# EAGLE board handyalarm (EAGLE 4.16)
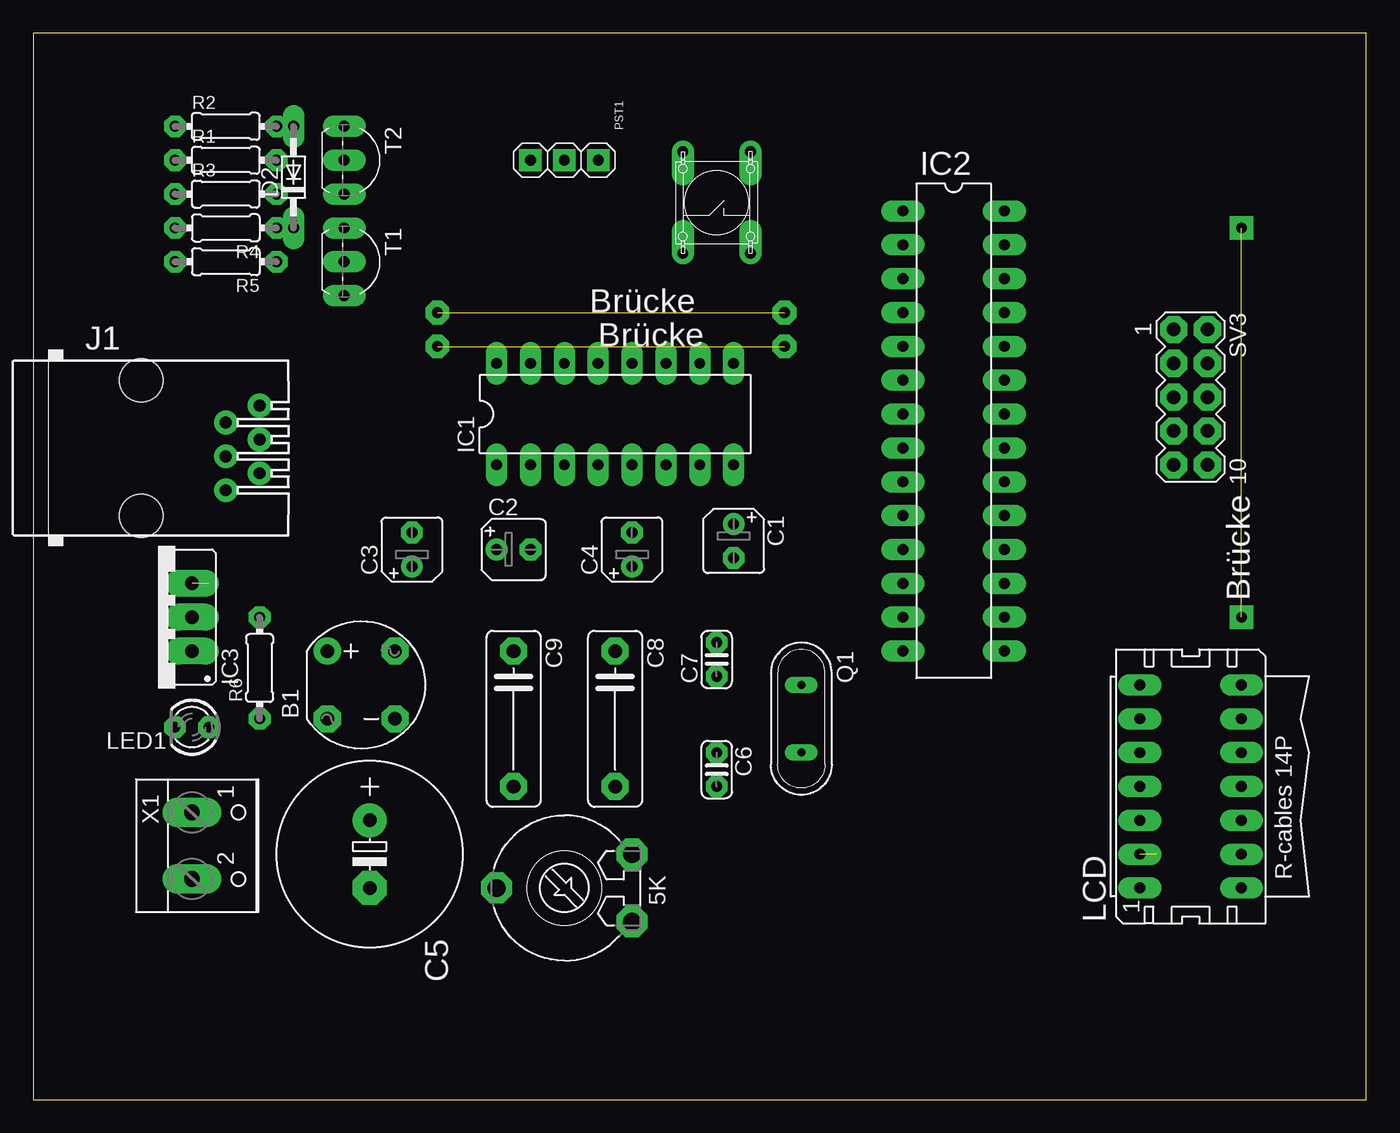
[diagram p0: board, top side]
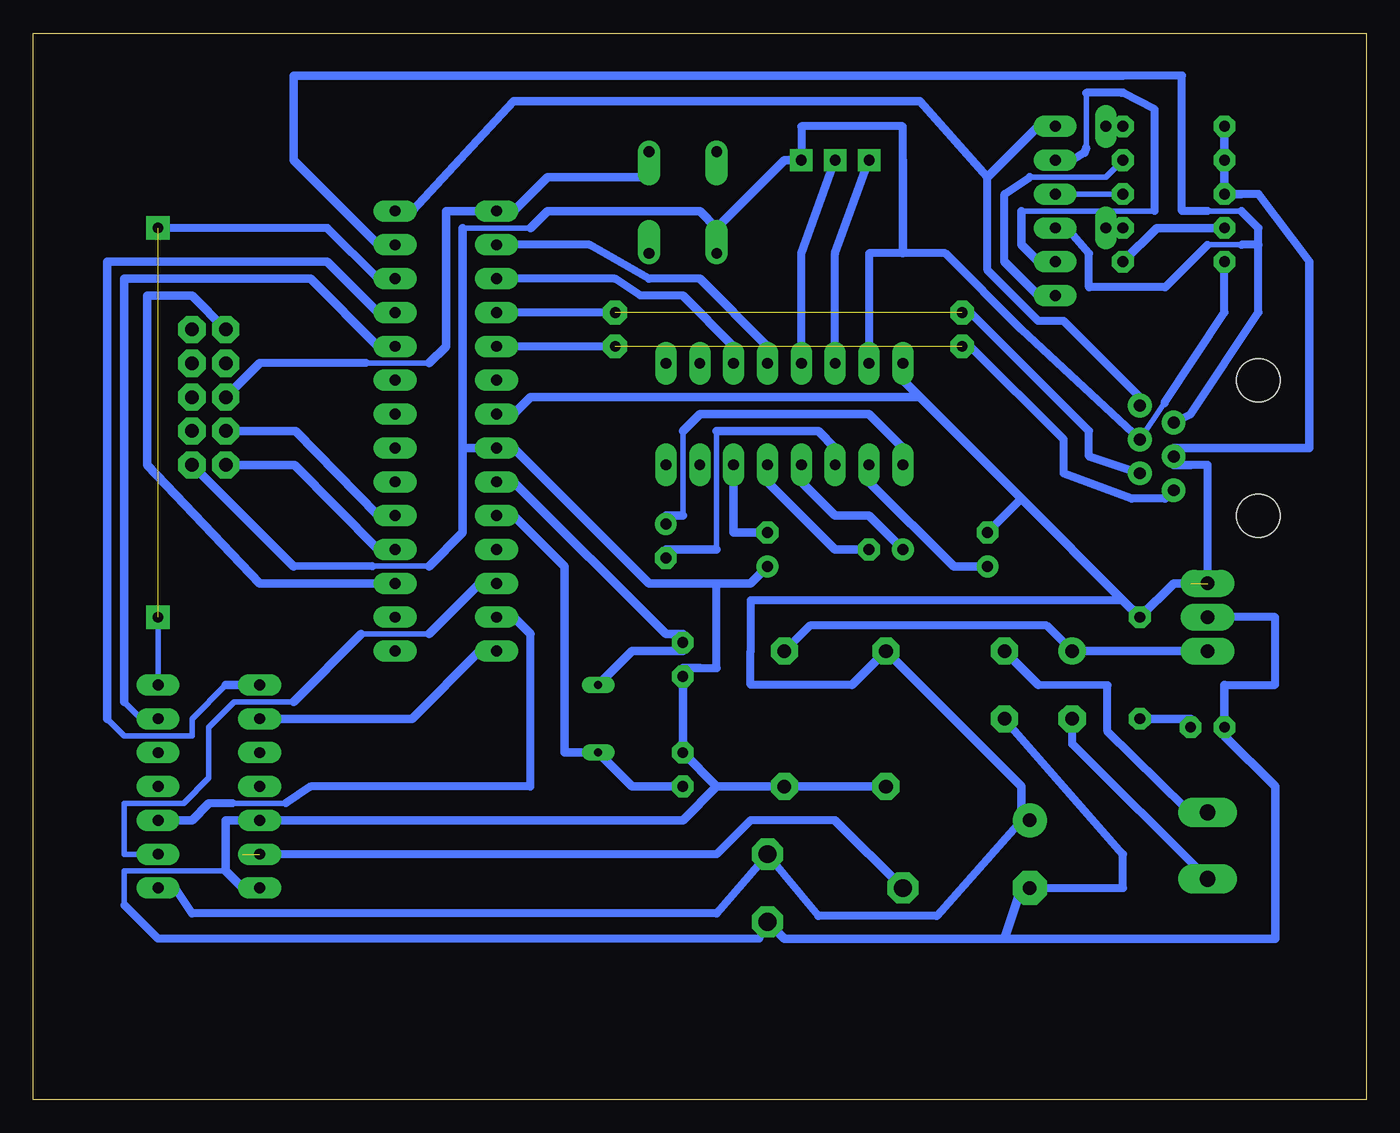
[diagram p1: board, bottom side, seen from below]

Size 100 x 80 mm. Coordinates in mm from the lower left corner, seen from the top.
Outline: 0,0 100,0 100,80 0,80 0,0
Copper layers (1*16): Top 0.035mm / dielectric 1.5mm / Bottom 0.035mm
Design rules "0,6mmleiterbahn": minimum track width 25mil, minimum drill 24mil, track to track 20mil, track to pad 20mil, pad to pad 20mil, via to via 8mil, smd to smd 8mil, copper to edge 40mil, drill to drill 8mil, minimum pad ring 10mil, minimum via ring 8mil, stop-mask expansion 4mil, vias tented up to drill 0mil, thermal gap 10mil

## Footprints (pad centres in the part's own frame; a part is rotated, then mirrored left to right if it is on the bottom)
LI10 = drill 1.321 octagon: A -2.54,-5.08; E 2.54,-5.08; S 0,5.08
RB1A = drill 1.016 round: + -2.54,2.54 | drill 1.016 octagon: - 2.54,-2.54; AC1 2.54,2.54; AC2 -2.54,-2.54
B45181A = drill 0.813 pad 1.6 round: + -1.27,0 | drill 0.813 pad 1.6 octagon: - 1.27,0
E5-13 = drill 1.016 pad 2.54 round: + -2.54,0 | drill 1.016 pad 2.54 octagon: - 2.54,0
C025-024X044 = drill 0.813 octagon: 1 -1.27,0; 2 1.27,0
C102-043X133 = drill 1.016 octagon: 1 -5.08,0; 2 5.08,0
DO34-7 = drill 0.813 long: A 3.81,0; C -3.81,0
DIL16 = drill 0.813 long: 1 -8.89,-3.81; 2 -6.35,-3.81; 3 -3.81,-3.81; 4 -1.27,-3.81; 5 1.27,-3.81; 6 3.81,-3.81; 7 6.35,-3.81; 8 8.89,-3.81; 9 8.89,3.81; 10 6.35,3.81; 11 3.81,3.81; 12 1.27,3.81; 13 -1.27,3.81; 14 -3.81,3.81; 15 -6.35,3.81; 16 -8.89,3.81
DIL28-3 = drill 0.813 long: 1 -16.51,-3.81; 2 -13.97,-3.81; 3 -11.43,-3.81; 4 -8.89,-3.81; 5 -6.35,-3.81; 6 -3.81,-3.81; 7 -1.27,-3.81; 8 1.27,-3.81; 9 3.81,-3.81; 10 6.35,-3.81; 11 8.89,-3.81; 12 11.43,-3.81; 13 13.97,-3.81; 14 16.51,-3.81; 15 16.51,3.81; 16 13.97,3.81; 17 11.43,3.81; 18 8.89,3.81; 19 6.35,3.81; 20 3.81,3.81; 21 1.27,3.81; 22 -1.27,3.81; 23 -3.81,3.81; 24 -6.35,3.81; 25 -8.89,3.81; 26 -11.43,3.81; 27 -13.97,3.81; 28 -16.51,3.81
78XXS = drill 1.016 long: GND 0,-2.54; IN -2.54,-2.54; OUT 2.54,-2.54
520250-3 = drill 0.889 round: 1 -3.175,8.89; 2 -1.905,6.35; 3 -0.635,8.89; 4 0.635,6.35; 5 1.905,8.89; 6 3.175,6.35 | hole 3.251: -5.08,0; 5.08,0
14P = drill 0.813 long: 1 -7.62,3.81; 2 -7.62,-3.81; 3 -5.08,3.81; 4 -5.08,-3.81; 5 -2.54,3.81; 6 -2.54,-3.81; 7 0,3.81; 8 0,-3.81; 9 2.54,3.81; 10 2.54,-3.81; 11 5.08,3.81; 12 5.08,-3.81; 13 7.62,3.81; 14 7.62,-3.81
LED3MM = drill 0.813 octagon: A -1.27,0; K 1.27,0
PFST-1-3 = drill 0.8 pad 1.676 square: 1 2.54,2.54; 2 2.54,0; 3 2.54,-2.54
QS = drill 0.61 long: 1 -2.54,0; 2 2.54,0
0204/7 = drill 0.813 octagon: 1 -3.81,0; 2 3.81,0
MA05-2 = drill 1.016 octagon: 1 -5.08,-1.27; 2 -5.08,1.27; 3 -2.54,-1.27; 4 -2.54,1.27; 5 0,-1.27; 6 0,1.27; 7 2.54,-1.27; 8 2.54,1.27; 9 5.08,-1.27; 10 5.08,1.27
TO92-EBC = drill 0.813 long: B 0,-1.27; C -2.54,-1.27; E 2.54,-1.27
TASTER = drill 0.8 pad 1.676 offset: 1 -2.54,2.54; 2 5.08,2.54; 3 -2.54,-2.54; 4 5.08,-2.54
W237-102 = drill 1.194 long: 1 -2.5,-1.27; 2 2.5,-1.27

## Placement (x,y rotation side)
5K  [LI10]  39.84,15.87 90 top
B1  RECTIFIER-RB1A  [RB1A]  24.6,31.11 0 top
C1  [B45181A]  52.54,41.91 270 top
C2  [B45181A]  36.03,41.27 0 top
C3  [B45181A]  28.41,41.27 90 top
C4  [B45181A]  44.92,41.27 90 top
C5  [E5-13]  25.23,18.41 270 top
C6  22p  [C025-024X044]  51.27,24.76 270 top
C7  22p  [C025-024X044]  51.27,33.02 90 top
C8  100n  [C102-043X133]  43.65,28.57 270 top
C9  100n  [C102-043X133]  36.03,28.57 270 top
D2  BAS15  [DO34-7]  19.52,69.21 90 top
IC1  MAX232  [DIL16]  43.65,51.43 0 top
IC2  MEGA8-P  [DIL28-3]  69.05,50.16 270 top
IC3  [78XXS]  9.36,36.19 90 top
J1  [520250-3]  8.09,48.89 270 top
LCD  [14P]  86.83,23.49 90 top
LED1  [LED3MM]  11.9,27.93 180 top
PST1  RS232  [PFST-1-3]  39.84,73.02 270 top
Q1  8MHZ  [QS]  57.62,28.57 270 top
R1  100  [0204/7]  14.44,70.48 0 top
R2  1k  [0204/7]  14.44,73.02 0 top
R3  100  [0204/7]  14.44,67.94 0 top
R4  3k3  [0204/7]  14.44,65.4 180 top
R5  330  [0204/7]  14.44,62.86 180 top
R6  [0204/7]  16.98,32.38 90 top
SV3  ISP  [MA05-2]  86.83,52.7 270 top
T1  BC557  [TO92-EBC]  24.6,62.86 270 top
T2  BC557  [TO92-EBC]  24.6,70.48 270 top
TA1  TASTER  [TASTER]  51.27,66.03 90 top
X1  [W237-102]  13.17,19.04 270 top

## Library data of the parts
5K = pot
B1 = rectifier
C1-C7 IC1-IC3 LED1 R1-R6 X1 = mega8modul
C8 C9 = rcl
D2 = diode
J1 = con-amp
LCD = con-dil
PST1 TA1 = mylib-gg
Q1 = special
SV3 = con-lstb
T1 T2 = transistor

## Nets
GND: 5K.A B1.- C4.+ C5.- C6.1 C7.1 C8.2 C9.2 IC1.15 IC2.8 IC3.GND J1.3 LCD.1 LCD.5 LED1.K PST1.1 R5.2 SV3.10 TA1.1
N$1: R1.2 T1.E
N$2: D2.A R2.2
N$3: D2.C R4.1 T1.B T2.B
N$4: R3.2 T2.E
N$5: R4.2 R5.1
N$6: C3.+ IC1.2
N$7: IC2.27 J1.2 T1.C
N$8: IC2.28 J1.1 T2.C
N$9: C4.- IC1.6
N$10: C1.- IC1.3
N$11: C1.+ IC1.1
N$12: C2.+ IC1.4
N$13: C2.- IC1.5
N$14: IC1.13 PST1.2
N$15: IC1.14 PST1.3
N$16: IC1.11 IC2.3
N$17: IC1.12 IC2.2
N$18: C7.2 IC2.9 Q1.1
N$19: IC2.25 LCD.13
N$20: IC2.14 LCD.11
N$21: IC2.4 J1.5
N$22: IC2.26 LCD.14
N$23: IC2.24 LCD.12
N$24: IC2.13 LCD.6
N$25: IC2.12 LCD.4
N$26: IC2.1 SV3.5 TA1.4
N$27: B1.+ C8.1 IC3.IN
N$28: B1.AC1 X1.1
N$29: B1.AC2 X1.2
N$30: LED1.A R6.1
N$31: IC2.5 J1.6
N$32: C6.2 IC2.10 Q1.2
N$49: IC2.17 SV3.1
N$50: IC2.18 SV3.9
N$51: IC2.19 SV3.7
N$53: 5K.S LCD.3
VCC: 5K.E C3.- C5.+ C9.1 IC1.16 IC2.7 IC3.OUT J1.4 LCD.2 R1.1 R2.1 R3.1 R6.2

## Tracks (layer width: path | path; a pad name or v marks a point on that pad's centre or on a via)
GND
  Bottom 0.406: 67.78,65.4 62.7,65.4 | 93.18,14.6 93.18,17.14 85.56,17.14 | 70.32,40 70.34,40.01 74.57,40.01 | J1.3 15.14,52.26
  Bottom 0.61: 37.3,55.88 37.3,63.5 34.76,63.5 31.58,63.5 25.87,57.78 J1.3 | R5.2 10.63,59.05 15.14,52.26 | 5K.A 45.55,12.06 90.64,12.06 90.66,12.1 93.18,14.6 | B1.- 18.25,18.41 18.25,15.87 25.87,15.87 | 50,32.38 48.73,32.38 48.73,38.73 | 10.63,31.11 6.82,31.11 6.82,36.19 IC3.GND | 70.32,40 70.3,40.01 | 74.57,40.01 80.48,40 | 34.76,70.48 34.76,73.02 42.38,73.02 PST1.1
  Bottom 0.635: 10.63,31.11 LED1.K 10.63,27.3 6.82,23.49 6.82,12.06 27.14,12.06 | 5K.A 43.65,12.06 27.14,12.06 | 27.14,12.06 25.87,15.87 C5.- | 48.73,65.4 43.65,70.48 PST1.1 | IC1.15 37.3,55.88 37.3,56.51 | 34.76,63.5 34.76,70.48 | C4.+ 46.19,38.73 48.73,38.73 53.81,38.73 63.97,48.89 IC2.8 67.78,48.89 | 80.48,40 SV3.10 | 70.32,40 67.78,42.54 67.78,48.89 | LCD.1 84.29,15.87 85.56,17.14 85.56,20.95 LCD.5 51.27,20.95 48.73,23.49 | C9.2 C8.2 48.73,23.49 | 48.73,23.49 C6.1 C7.1 51.27,32.38 50,32.38 | 48.73,65.4 50,66.67 61.43,66.67 62.7,65.4 | 67.78,48.89 67.78,65.4 | 48.73,65.4 TA1.1
N$1
  Bottom 0.406: R1.2 19.52,69.21 25.23,69.21
  Bottom 0.61: 25.23,69.21 27.14,67.94 27.14,62.86
  Bottom 0.635: 27.14,62.86 24.6,60.32 T1.E
N$2
  Bottom 0.635: D2.A R2.2
N$3
  Bottom 0.406: 25.87,66.67 19.52,66.67 15.87,66.67 | 21.01,75.53 21.01,71.44 | 18.25,75.56 18.34,75.53
  Bottom 0.61: 18.25,75.56 15.87,74.29 15.87,66.67 | 22.06,70.48 21.14,71.04 21.01,71.44 | 18.34,75.53 21.01,75.53
  Bottom 0.635: R4.1 D2.C 19.52,66.67 | 25.87,66.67 25.87,64.13 24.6,62.86 T1.B | 22.06,70.48 T2.B
N$4
  Bottom 0.406: R3.2 T2.E
N$5
  Bottom 0.635: R4.2 15.71,65.4 R5.1
N$6
  Bottom 0.635: C3.+ 30.95,40 37.3,46.35 IC1.2
N$7
  Bottom 0.406: 9.36,64.13 11.9,64.13 | 9.36,66.67 11.9,66.67
  Bottom 0.61: 11.9,66.67 13.83,66.67 13.83,76.83 18.25,76.83 | 8.09,64.13 8.09,59.05 13.17,51.43 J1.2 | 8.09,64.13 8.09,65.4 9.36,66.67 | 8.09,64.13 9.36,64.13 | 11.9,64.13 15.08,60.96 20.79,60.96 20.79,63.5 22.43,65.39 23.32,65.44 T1.C
  Bottom 0.635: 18.25,76.83 80.48,76.83 80.48,70.48 74.13,64.13 IC2.27
N$8
  Bottom 0.61: 28.41,69.21 28.41,62.23 24.6,58.41 22.7,58.41 16.98,52.7
  Bottom 0.635: T2.C 24.6,73.02 28.41,69.21 33.49,74.92 63.97,74.92 71.59,66.67 IC2.28 | J1.1 16.98,52.7
N$9
  Bottom 0.635: C4.- 47.46,42.54 IC1.6
N$10
  Bottom 0.406: 48.73,50.16 48.73,41.27
  Bottom 0.635: 48.73,50.16 41.11,50.16 39.84,48.89 IC1.3 | 48.73,41.27 52.54,41.27 C1.-
N$11
  Bottom 0.406: 51.27,50.16 51.27,43.81
  Bottom 0.635: 51.27,50.16 50,51.43 37.3,51.43 34.76,48.89 IC1.1 | 51.27,43.81 52.54,43.81 C1.+
N$12
  Bottom 0.635: C2.+ 37.3,43.81 39.84,43.81 42.38,46.35 IC1.4
N$13
  Bottom 0.635: C2.- 39.84,41.27 44.92,46.35 IC1.5
N$14
  Bottom 0.61: IC1.13 42.38,63.5 PST1.2
N$15
  Bottom 0.61: IC1.14 39.84,63.5 PST1.3
N$16
  Bottom 0.61: IC2.3 56.35,61.59 54.45,60.32 51.27,60.32
  Bottom 0.635: 51.27,60.32 47.46,56.51 IC1.11 | IC2.3 63.97,61.59
N$17
  Bottom 0.61: 50,61.59 53.81,61.59 58.25,64.13 IC2.2
  Bottom 0.635: 50,61.59 44.92,56.51 IC1.12 | IC2.2 63.97,64.13
N$18
  Bottom 0.635: Q1.1 55.08,33.65 51.27,33.65 C7.2 51.27,34.92 52.54,34.92 63.97,46.35 IC2.9
N$19
  Bottom 0.406: 85.56,31.11 88.1,28.57 88.1,27.3 93.18,27.3 94.45,28.57
  Bottom 0.635: 94.45,28.57 94.45,62.86 77.94,62.86 74.13,59.05 IC2.25 | LCD.13 85.56,31.11
N$20
  Bottom 0.635: IC2.14 66.51,33.65 71.59,28.57 LCD.11
N$21  (1 unrouted)
  Bottom 0.61: 56.35,59.05 IC2.4 | J1.5 20.79,48.26 20.79,50.16 29.68,59.05 30.31,59.05
N$22  (1 unrouted)
  Bottom 0.406: IC2.26 74.13,61.59 | LCD.14 90.64,36.19
  Bottom 0.61: 74.13,61.59 77.94,65.4 90.64,65.4
N$23
  Bottom 0.406: 91.91,28.57 93.18,29.84
  Bottom 0.635: 93.18,29.84 93.18,61.59 79.21,61.59 74.13,56.51 IC2.24 | LCD.12 91.91,28.57
N$24
  Bottom 0.406: 81.06,22.23 85.06,22.23
  Bottom 0.61: 85.06,22.23 86.83,22.22 | 81.06,22.23 79.21,23.49 62.7,23.48 62.7,34.92
  Bottom 0.635: 62.7,34.92 63.97,36.19 IC2.13 | 86.83,22.22 88.1,20.95 LCD.6
N$25
  Bottom 0.406: 70.32,34.92 75.4,34.92 | LCD.4 93.18,18.41 93.18,22.22 88.73,22.22 86.83,24.12 86.83,27.93 84.92,29.84 80.48,29.84
  Bottom 0.635: 70.32,34.92 66.51,38.73 IC2.12 | 75.4,34.92 80.48,29.84
N$26
  Bottom 0.406: 70.3,55.26 | 70.3,55.26 75.06,55.26
  Bottom 0.61: 75.06,55.26 83.02,55.24
  Bottom 0.635: TA1.4 53.81,69.21 61.43,69.21 63.97,66.67 IC2.1 69.05,66.67 69.05,56.51 70.3,55.26 70.32,55.24 | 83.02,55.24 SV3.5
N$27
  Bottom 0.61: B1.+ 23.96,35.55 41.74,35.55 C8.1
  Bottom 0.635: IC3.IN B1.+
N$28
  Bottom 0.61: 24.6,31.11 19.41,31.08 19.41,27.61 13.54,21.83 11.89,21.61 X1.1
  Bottom 0.635: 24.6,31.11 B1.AC1
N$29
  Bottom 0.61: X1.2 22.06,26.66 B1.AC2
N$30
  Bottom 0.635: R6.1 13.17,28.57 LED1.A
N$31  (1 unrouted)
  Bottom 0.61: 56.35,56.51 IC2.5 | 30.31,56.51 29.68,56.51 22.7,49.53 22.7,46.98 17.61,45.08 15.08,45.08 J1.6
N$32
  Bottom 0.635: C6.2 55.08,23.49 Q1.2 60.16,26.03 60.16,40 63.97,43.81 IC2.10
N$33  (via drill 0.8 pad 1.78)
  other vias: 90.64,36.19
N$34  (via drill 0.8 pad 1.78)
  other vias: 90.64,65.4
N$35  (via drill 0.8 pad 1.78)
  other vias: 30.31,59.05
N$36  (via drill 0.8 pad 1.78)
  other vias: 30.31,56.51
N$37  (via drill 0.8 pad 1.78)
  other vias: 56.35,59.05
N$38  (via drill 0.8 pad 1.78)
  other vias: 56.35,56.51
N$49
  Bottom 0.635: SV3.1 88.1,60.32 91.44,60.32 91.44,47.62 83.02,38.73 IC2.17
N$50
  Bottom 0.635: SV3.9 80.39,47.62 74.13,41.27 IC2.18
N$51
  Bottom 0.635: SV3.7 80.3,50.16 74.13,43.81 IC2.19
N$53  (1 unrouted)
  Bottom 0.61: 39.84,20.95 46.19,20.95 48.73,18.41 84.29,18.41
  Bottom 0.635: 5K.S 39.84,20.95 | LCD.3 81.75,18.41
VCC  (1 unrouted)
  Bottom 0.61: 25.87,45.08 C3.- | 38.57,31.11 43.65,31.11 46.19,31.11 46.19,33.65 46.19,37.46 18.25,37.46 | 9.36,67.94 8.09,67.94 4.28,62.86 | 89.37,15.87 88.1,13.97 48.73,13.97 5K.E 41.11,13.78 32.22,13.78 25.87,20.95 | 13.17,47.62 11.9,47.62 IC3.OUT
  Bottom 0.635: 89.37,15.87 LCD.2 | C5.+ 25.87,20.95 25.87,23.49 C9.1 38.57,31.11 | R2.1 R1.1 R3.1 9.36,67.94 | 13.17,38.73 14.44,38.73 R6.2 18.25,37.46 25.87,45.08 33.49,52.7 | 33.49,52.7 34.76,53.97 IC1.16 | 33.49,52.7 62.7,52.7 63.97,51.43 IC2.7 | 13.17,47.62 14.44,47.62 J1.4 14.44,48.89 4.28,48.89 4.28,62.86

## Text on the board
tPlace: Brücke | Brücke | Brücke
